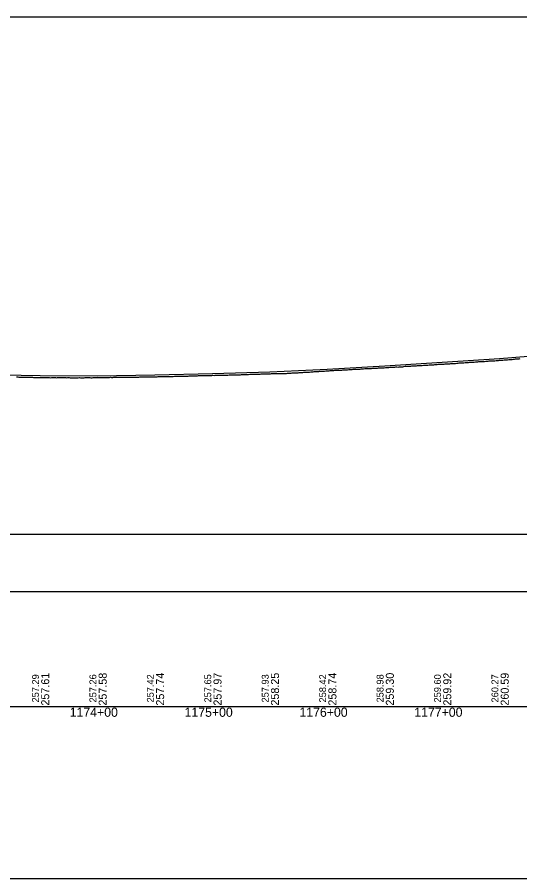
# Model space of a CAD drawing. Extents: x 2898 to 49495, y -15038 to -13538.
# Drawn here: x 6683 to 7121, y -15038 to -14288 of the extents above; entities that cross this region are included whole.
import ezdxf

# ---------------------------------------------------------------- set-up
doc = ezdxf.new("R2010")
doc.units = 0
for name, color, linetype in [('RD_DDB_Profile_EX', 7, 'Continuous'), ('RD_DDB_Profile_PR', 7, 'Continuous'), ('RD_DDB_StaTX', 7, 'Continuous'), ('RD_DDB_StripGrade', 7, 'Continuous'), ('RD_GPK_Profile_Cell', 7, 'Continuous'), ('RD_SHT_ShtClip', 7, 'Continuous')]:
    doc.layers.add(name, color=color, linetype=linetype)

msp = doc.modelspace()

# ---------------------------------------------------------------- linework, layer by layer
at = {"layer": 'RD_DDB_Profile_EX'}
for points in [[(7050.09, -14590.58), (7051.09, -14590.53), (7052.1, -14590.53), (7053.09, -14590.48), (7054.09, -14590.38), (7055.09, -14590.38), (7056.1, -14590.33), (7057.09, -14590.28), (7058.09, -14590.28), (7059.1, -14590.18), (7060.1, -14590.08), (7061.09, -14589.98), (7062.09, -14589.93), (7063.1, -14589.88), (7064.1, -14589.78), (7065.09, -14589.78), (7066.09, -14589.68), (7067.34, -14589.54), (7068.34, -14589.44), (7069.33, -14589.44), (7070.34, -14589.39), (7071.34, -14589.34), (7072.34, -14589.19), (7073.34, -14589.14), (7074.34, -14589.08), (7075.34, -14588.99), (7076.33, -14588.94), (7077.34, -14588.88), (7078.34, -14588.84), (7079.34, -14588.78), (7080.34, -14588.73), (7081.34, -14588.63), (7082.34, -14588.58), (7083.33, -14588.43), (7084.34, -14588.34), (7085.34, -14588.28), (7086.34, -14588.28), (7087.34, -14588.23), (7088.34, -14588.13), (7089.34, -14588.08), (7090.33, -14588.03), (7091.34, -14587.98), (7092.34, -14587.98), (7093.34, -14587.88), (7094.33, -14587.68), (7095.34, -14587.63), (7096.34, -14587.58), (7097.33, -14587.53), (7098.34, -14587.58), (7099.34, -14587.48), (7100.34, -14587.43), (7101.34, -14587.33), (7102.34, -14587.18), (7103.34, -14587.13), (7104.33, -14587.08), (7105.34, -14586.98), (7106.34, -14586.93), (7107.34, -14586.83), (7108.34, -14586.68), (7109.34, -14586.68), (7110.34, -14586.58), (7111.33, -14586.43), (7112.34, -14586.38), (7113.34, -14586.38), (7114.33, -14586.33), (7115.33, -14586.18), (7116.34, -14586.08), (7117.34, -14585.98), (7118.33, -14585.93), (7119.34, -14585.83), (7120.34, -14585.78), (7121.33, -14585.68)], [(6950.06, -14596.48), (6951.06, -14596.48), (6952.05, -14596.43), (6953.05, -14596.38), (6954.06, -14596.33), (6955.05, -14596.23), (6956.05, -14596.13), (6957.05, -14596.08), (6958.06, -14595.98), (6959.05, -14595.93), (6960.05, -14595.83), (6961.05, -14595.83), (6962.06, -14595.78), (6963.05, -14595.73), (6964.05, -14595.68), (6965.05, -14595.63), (6966.06, -14595.58), (6967.05, -14595.48), (6968.05, -14595.43), (6969.06, -14595.33), (6970.05, -14595.28), (6971.05, -14595.28), (6972.05, -14595.23), (6973.06, -14595.18), (6974.05, -14595.13), (6975.05, -14595.08), (6976.05, -14594.98), (6977.05, -14594.98), (6978.05, -14594.93), (6979.05, -14594.83), (6980.05, -14594.78), (6981.04, -14594.78), (6982.05, -14594.73), (6983.05, -14594.68), (6984.05, -14594.63), (6985.04, -14594.48), (6986.05, -14594.38), (6987.05, -14594.38), (6988.05, -14594.33), (6989.04, -14594.33), (6990.05, -14594.32), (6991.05, -14594.22), (6992.04, -14594.17), (6993.04, -14594.07), (6994.05, -14594.02), (6995.05, -14593.97), (6996.04, -14593.97), (6997.04, -14593.92), (6998.05, -14593.82), (6999.05, -14593.77), (7000.04, -14593.67), (7001.04, -14593.67), (7002.05, -14593.67), (7003.04, -14593.62), (7004.04, -14593.42), (7005.04, -14593.32), (7006.05, -14593.32), (7007.04, -14593.32), (7008.04, -14593.22), (7009.04, -14593.17), (7010.09, -14593.12), (7011.09, -14593.12), (7012.09, -14593.02), (7013.08, -14592.92), (7014.08, -14592.92), (7015.09, -14593.02), (7016.09, -14592.77), (7017.08, -14592.72), (7018.08, -14592.77), (7019.09, -14592.67), (7020.09, -14592.52), (7021.22, -14592.37), (7022.08, -14592.37), (7023.09, -14592.32), (7024.09, -14592.27), (7025.08, -14592.22), (7026.08, -14592.17), (7027.09, -14592.07), (7028.09, -14592.07), (7029.08, -14592.02), (7030.08, -14591.87), (7031.09, -14591.82), (7032.09, -14591.77), (7033.08, -14591.72), (7034.09, -14591.67), (7035.09, -14591.67), (7036.09, -14591.62), (7037.08, -14591.47), (7038.09, -14591.47), (7039.09, -14591.42), (7040.09, -14591.32), (7041.09, -14591.22), (7042.09, -14591.18), (7043.09, -14591.08), (7044.09, -14591.08), (7045.09, -14591.08), (7046.09, -14590.98), (7047.09, -14590.88), (7048.1, -14590.88), (7049.09, -14590.78), (7050.09, -14590.58)], [(6682.96, -14601.65), (6683.97, -14601.65), (6684.97, -14601.7), (6685.97, -14601.7), (6686.96, -14601.74), (6687.97, -14601.74), (6688.97, -14601.74), (6689.96, -14601.75), (6690.69, -14601.8), (6691.69, -14601.8), (6692.69, -14601.85), (6693.69, -14601.89), (6694.69, -14601.94), (6695.7, -14601.94), (6696.69, -14601.94), (6697.69, -14601.99), (6698.69, -14602.04), (6699.69, -14601.99), (6700.69, -14602.04), (6701.69, -14602.04), (6702.7, -14601.99), (6703.69, -14602.04), (6704.69, -14602.04), (6705.69, -14602.09), (6706.69, -14602.09), (6707.69, -14602.14), (6708.69, -14602.14), (6709.69, -14602.14), (6710.69, -14602.14), (6711.69, -14602.19), (6712.69, -14602.24), (6713.69, -14602.19), (6714.69, -14602.14), (6715.69, -14602.14), (6716.69, -14602.19), (6717.69, -14602.24), (6718.69, -14602.19), (6719.68, -14602.19), (6720.69, -14602.19), (6721.69, -14602.14), (6722.69, -14602.14), (6723.68, -14602.19), (6724.69, -14602.19), (6725.69, -14602.19), (6726.68, -14602.24), (6727.69, -14602.19), (6728.69, -14602.19), (6729.69, -14602.24), (6730.68, -14602.24), (6731.69, -14602.29), (6732.69, -14602.33), (6733.68, -14602.33), (6734.68, -14602.24), (6735.69, -14602.24), (6736.68, -14602.28), (6737.68, -14602.23), (6738.68, -14602.24), (6739.69, -14602.28), (6740.68, -14602.28), (6741.68, -14602.28), (6742.69, -14602.23), (6743.68, -14602.23), (6744.68, -14602.23), (6745.68, -14602.23), (6746.69, -14602.23), (6747.68, -14602.28), (6748.68, -14602.28), (6749.69, -14602.23), (6750.68, -14602.23)], [(6750.68, -14602.23), (6751.68, -14602.18), (6752.68, -14602.18), (6753.68, -14602.18), (6754.68, -14602.13), (6755.68, -14602.13), (6756.69, -14602.13), (6757.68, -14602.08), (6758.68, -14602.08), (6759.68, -14602.08), (6760.68, -14602.08), (6761.68, -14602.03), (6762.68, -14601.98), (6763.68, -14601.98), (6764.68, -14601.93), (6765.68, -14601.98), (6766.68, -14601.98), (6767.68, -14601.93), (6768.32, -14601.93), (6769.33, -14601.93), (6770.32, -14601.93), (6771.32, -14601.88), (6772.32, -14601.93), (6773.32, -14601.93), (6774.32, -14601.93), (6775.32, -14601.93), (6776.33, -14601.83), (6777.32, -14601.83), (6778.32, -14601.87), (6779.32, -14601.82), (6780.31, -14601.82), (6781.32, -14601.77), (6782.32, -14601.72), (6783.31, -14601.72), (6784.32, -14601.72), (6785.32, -14601.77), (6786.31, -14601.72), (6787.32, -14601.72), (6788.32, -14601.72), (6789.31, -14601.67), (6790.31, -14601.62), (6791.32, -14601.62), (6792.31, -14601.62), (6793.31, -14601.62), (6794.32, -14601.62), (6795.32, -14601.57), (6796.31, -14601.52), (6797.31, -14601.57), (6798.32, -14601.52), (6799.31, -14601.52), (6800.31, -14601.47), (6801.32, -14601.37), (6802.31, -14601.37), (6803.31, -14601.37), (6804.32, -14601.37), (6805.31, -14601.37), (6806.31, -14601.32), (6807.32, -14601.32), (6808.31, -14601.32), (6809.31, -14601.27), (6810.32, -14601.27), (6811.32, -14601.27), (6812.31, -14601.27), (6813.32, -14601.27), (6814.32, -14601.27), (6815.31, -14601.17), (6816.32, -14601.12), (6817.32, -14601.12), (6818.31, -14601.12), (6819.32, -14601.12), (6820.32, -14601.07), (6821.31, -14601.07), (6822.32, -14601.07), (6823.32, -14600.97), (6824.31, -14600.97), (6825.32, -14601.02), (6826.32, -14601.02), (6827.31, -14600.93), (6828.32, -14600.88), (6829.32, -14600.83), (6830.32, -14600.88), (6831.32, -14600.88), (6832.32, -14600.83), (6833.32, -14600.78), (6834.32, -14600.78), (6835.32, -14600.68), (6836.32, -14600.68), (6837.32, -14600.68), (6838.32, -14600.68), (6839.32, -14600.68), (6840.32, -14600.58), (6841.32, -14600.48), (6842.32, -14600.48), (6843.32, -14600.43), (6844.32, -14600.43), (6845.32, -14600.38), (6846.32, -14600.38), (6847.32, -14600.34), (6848.32, -14600.34), (6848.85, -14600.34), (6849.85, -14600.29)], [(6849.85, -14600.29), (6850.85, -14600.24), (6851.84, -14600.28), (6852.85, -14600.24), (6853.86, -14600.19), (6854.86, -14600.23), (6855.85, -14600.18), (6856.86, -14600.19), (6857.86, -14600.13), (6858.85, -14600.09), (6859.86, -14600.04), (6860.86, -14600.08), (6861.86, -14600.03), (6862.85, -14599.99), (6863.86, -14599.98), (6864.86, -14599.94), (6865.86, -14599.93), (6866.86, -14599.93), (6867.86, -14599.83), (6868.86, -14599.79), (6869.85, -14599.83), (6870.86, -14599.83), (6871.86, -14599.83), (6872.86, -14599.74), (6873.85, -14599.73), (6874.86, -14599.68), (6875.86, -14599.68), (6876.85, -14599.68), (6877.86, -14599.68), (6878.86, -14599.58), (6879.86, -14599.53), (6880.85, -14599.44), (6881.86, -14599.39), (6882.86, -14599.39), (6883.85, -14599.34), (6884.86, -14599.34), (6885.86, -14599.33), (6886.86, -14599.28), (6887.85, -14599.24), (6888.86, -14599.19), (6889.86, -14599.24), (6890.85, -14599.23), (6891.86, -14599.23), (6892.86, -14599.23), (6893.86, -14599.18), (6894.85, -14599.13), (6895.86, -14599.04), (6896.86, -14599.03), (6897.85, -14598.94), (6898.85, -14598.94), (6899.86, -14598.93), (6900.86, -14598.84), (6901.85, -14598.78), (6902.86, -14598.84), (6903.86, -14598.79), (6904.85, -14598.74), (6905.85, -14598.68), (6906.86, -14598.68), (6907.86, -14598.68), (6908.85, -14598.59), (6909.86, -14598.64), (6910.86, -14598.68), (6911.85, -14598.63), (6912.85, -14598.58), (6913.86, -14598.53), (6914.86, -14598.53), (6915.85, -14598.53), (6916.86, -14598.48), (6917.86, -14598.48), (6918.85, -14598.43), (6919.85, -14598.38), (6920.86, -14598.28), (6921.86, -14598.18), (6922.85, -14598.14), (6923.85, -14598.14), (6924.86, -14598.09), (6925.85, -14598.04), (6927.06, -14597.99), (6928.06, -14597.89), (6929.06, -14597.74), (6930.06, -14597.69), (6931.06, -14597.64), (6932.06, -14597.64), (6933.06, -14597.59), (6934.06, -14597.49), (6935.06, -14597.39), (6936.06, -14597.34), (6937.06, -14597.34), (6938.06, -14597.34), (6939.06, -14597.24), (6940.06, -14597.09), (6941.05, -14597.04), (6942.06, -14596.99), (6943.06, -14596.98), (6944.05, -14596.94), (6945.05, -14596.93), (6946.06, -14596.78), (6947.06, -14596.69), (6948.05, -14596.59), (6949.05, -14596.48), (6950.06, -14596.48)]]:
    msp.add_lwpolyline(points, dxfattribs=at)
at = {"layer": 'RD_DDB_Profile_PR'}
msp.add_lwpolyline([(6653.38, -14599.42), (6703.38, -14600.43), (6753.38, -14600.58), (6803.38, -14599.77), (6853.38, -14598.61), (6903.38, -14597.21), (6953.38, -14594.77), (7003.38, -14591.95), (7053.38, -14588.85), (7103.38, -14585.53), (7153.38, -14581.57), (7203.38, -14577.76), (7253.38, -14574.1), (7303.38, -14570.42), (7353.38, -14566.57), (7403.38, -14562.58), (7453.38, -14558.69), (7503.38, -14554.95), (7553.38, -14551.64), (7603.38, -14547.74)], dxfattribs=at)
at = {"layer": 'RD_GPK_Profile_Cell'}
msp.add_line((2976.05, -14888.47), (48721.13, -14888.47), dxfattribs=at)
at = {"layer": 'RD_SHT_ShtClip'}
for points in [[(7476.22, -14788.47), (7476.22, -14288.47), (7476.22, -14288.47), (5976.38, -14288.47), (5976.38, -14788.47)], [(5956.38, -14738.47), (7496.05, -14738.47), (7496.05, -15038.47), (5956.38, -15038.47)]]:
    msp.add_lwpolyline(points, close=True, dxfattribs=at)

# ---------------------------------------------------------------- texts
at = {"layer": 'RD_DDB_StaTX'}
for s, p in [('1174+00', (6729.18, -14897.47)), ('1175+00', (6829.18, -14897.47)), ('1176+00', (6929.18, -14897.47)), ('1177+00', (7029.18, -14897.47))]:
    msp.add_text(s, height=8, dxfattribs=at).set_placement(p)
at = {"layer": 'RD_DDB_StripGrade'}
for s, height, p in [('257.29', 6, (6702.38, -14884.98)), ('257.61', 7, (6711.38, -14887.72)), ('257.26', 6, (6752.38, -14884.98)), ('257.58', 7, (6761.38, -14887.72)), ('257.42', 6, (6802.38, -14884.98)), ('257.74', 7, (6811.38, -14887.72)), ('257.65', 6, (6852.38, -14884.98)), ('257.97', 7, (6861.38, -14887.72)), ('257.93', 6, (6902.38, -14884.98)), ('258.25', 7, (6911.38, -14887.72)), ('258.42', 6, (6952.38, -14884.98)), ('258.74', 7, (6961.38, -14887.72)), ('258.98', 6, (7002.38, -14884.98)), ('259.30', 7, (7011.38, -14887.72)), ('259.60', 6, (7052.38, -14884.98)), ('259.92', 7, (7061.38, -14887.72)), ('260.27', 6, (7102.38, -14884.98)), ('260.59', 7, (7111.38, -14887.72))]:
    msp.add_text(s, height=height, rotation=90, dxfattribs=at).set_placement(p)

doc.saveas('drawing.dxf')
